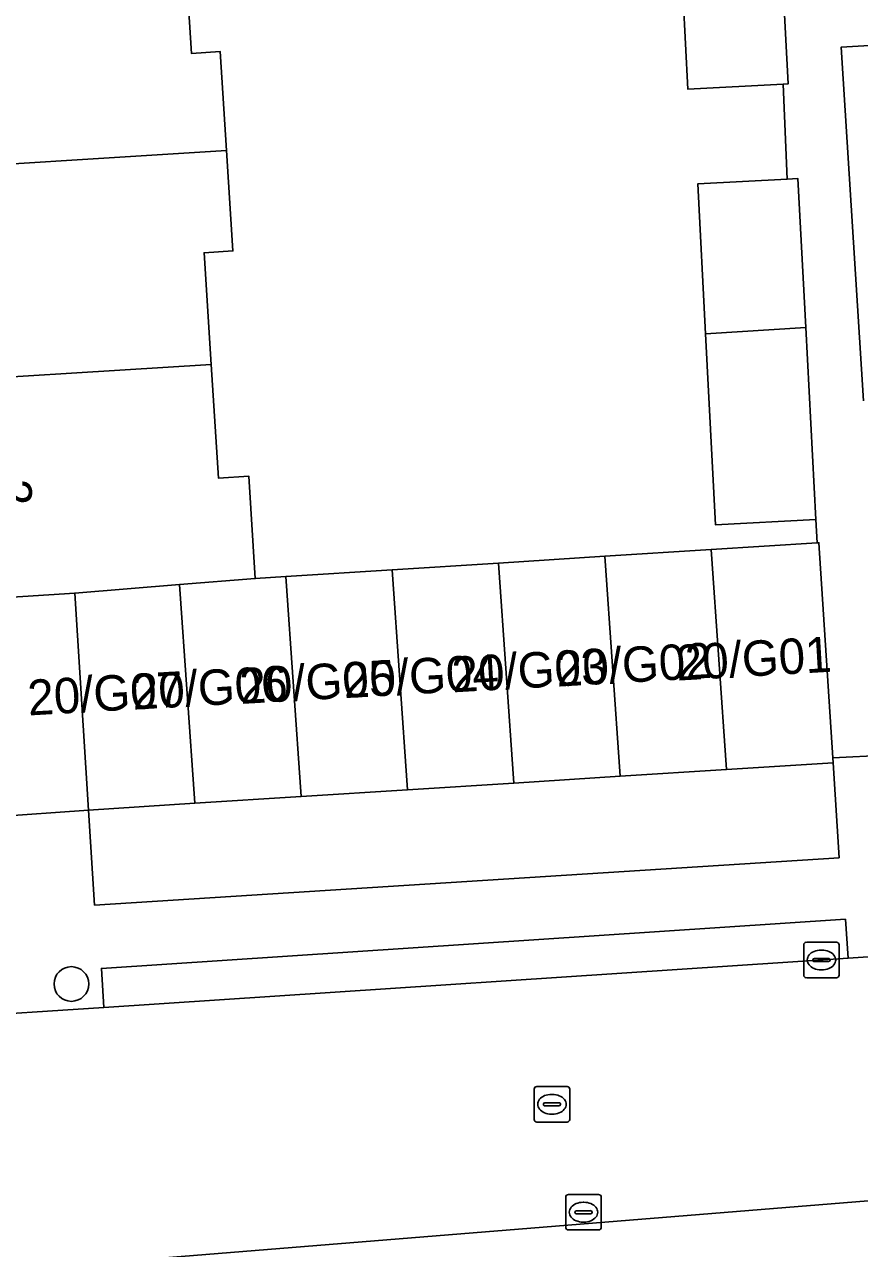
# Model space of a CAD drawing. Extents: x 159680 to 160786, y 387323 to 388340.
# Drawn here: x 160242.97 to 160266.51, y 387825.78 to 387860.29 of the extents above; entities that cross this region are included whole.
import ezdxf

# ---------------------------------------------------------------- set-up
doc = ezdxf.new("R2010")
doc.units = 0
for name, color, linetype in [('IMGEO_Boom', 7, 'Continuous'), ('IMGEO_Erf', 7, 'Continuous'), ('IMGEO_Kolk', 7, 'Continuous'), ('IMGEO_Pand', 7, 'Continuous'), ('IMGEO_Pand_nummerreeks', 7, 'Continuous'), ('IMGEO_Parkeervlak_open', 7, 'Continuous'), ('IMGEO_Rijbaan_lokaal_open', 7, 'Continuous'), ('IMGEO_Rioolput', 7, 'Continuous'), ('IMGEO_Voetpad_open', 7, 'Continuous')]:
    doc.layers.add(name, color=color, linetype=linetype)

msp = doc.modelspace()

# ---------------------------------------------------------------- linework, layer by layer
at = {"layer": 'IMGEO_Boom'}
msp.add_circle((160244.289, 387833.235), 0.489, dxfattribs=at)
at = {"layer": 'IMGEO_Erf'}
for points in [[(160247.466, 387862.725), (160247.672, 387859.477), (160248.484, 387859.529), (160248.662, 387856.736), (160248.842, 387853.906), (160248.032, 387853.854), (160248.232, 387850.704), (160248.436, 387847.502), (160249.288, 387847.556), (160249.471, 387844.669), (160250.333, 387844.724), (160253.332, 387844.914), (160256.33, 387845.105), (160259.328, 387845.295), (160262.327, 387845.486), (160265.313, 387845.676), (160265.271, 387846.329), (160262.449, 387846.182), (160262.168, 387851.571), (160261.948, 387855.798), (160264.463, 387855.929), (160264.358, 387858.608), (160261.669, 387858.468), (160261.402, 387863.592)], [(160239.442, 387837.76), (160244.771, 387838.139), (160244.382, 387844.258), (160239.539, 387843.95), (160239.52, 387844.246), (160239.862, 387844.268), (160239.639, 387847.766), (160238.976, 387847.724), (160238.956, 387848.036), (160239.268, 387848.056), (160239.136, 387850.138), (160239.003, 387852.22), (160238.723, 387852.202), (160238.702, 387852.539), (160239.332, 387852.579), (160239.117, 387855.96), (160238.75, 387855.937), (160238.738, 387856.118), (160238.727, 387856.298), (160239.079, 387856.32), (160238.861, 387859.753)], [(160267.111, 387859.715), (160265.991, 387859.653), (160266.622, 387849.679)]]:
    msp.add_lwpolyline(points, dxfattribs=at)
at = {"layer": 'IMGEO_Kolk'}
for p, q in [((160264.932, 387833.487), (160264.932, 387834.339)), ((160265.007, 387834.413), (160265.859, 387834.413)), ((160265.933, 387834.339), (160265.933, 387833.487)), ((160265.42, 387834.193), (160265.445, 387834.193)), ((160265.191, 387833.907), (160265.191, 387833.919)), ((160265.629, 387833.87), (160265.231, 387833.87)), ((160265.234, 387833.956), (160265.632, 387833.956)), ((160265.443, 387833.633), (160265.418, 387833.633)), ((160265.675, 387833.919), (160265.675, 387833.907)), ((160265.859, 387833.413), (160265.007, 387833.413)), ((160258.225, 387826.374), (160258.225, 387827.226)), ((160258.3, 387827.3), (160259.152, 387827.3)), ((160258.713, 387827.08), (160258.738, 387827.08)), ((160259.226, 387827.226), (160259.226, 387826.374)), ((160258.484, 387826.794), (160258.484, 387826.806)), ((160258.922, 387826.757), (160258.524, 387826.757)), ((160258.527, 387826.843), (160258.925, 387826.843)), ((160258.968, 387826.806), (160258.968, 387826.794)), ((160258.736, 387826.52), (160258.711, 387826.52)), ((160259.152, 387826.3), (160258.3, 387826.3))]:
    msp.add_line(p, q, dxfattribs=at)
for points in [[(160264.932, 387833.487), (160264.932, 387834.339)], [(160265.007, 387834.413), (160265.859, 387834.413)], [(160265.933, 387834.339), (160265.933, 387833.487)], [(160265.859, 387833.413), (160265.007, 387833.413)], [(160258.225, 387826.374), (160258.225, 387827.226)], [(160258.3, 387827.3), (160259.152, 387827.3)], [(160259.226, 387827.226), (160259.226, 387826.374)], [(160259.152, 387826.3), (160258.3, 387826.3)]]:
    msp.add_lwpolyline(points, dxfattribs=at)
for centre, radius, start, end in [((160265.009, 387834.337), 0.0765, 91.552, 178.448), ((160265.009, 387834.337), 0.0765, 91.552, 178.448), ((160265.857, 387834.337), 0.0765, 1.552, 88.448), ((160265.857, 387834.337), 0.0765, 1.552, 88.448), ((160265.231, 387833.916), 0.0403, 85.8775, 175.7526), ((160265.228, 387833.906), 0.0366, 178.938, 274.7102), ((160265.632, 387833.913), 0.043, 264.8664, 352.4533), ((160265.636, 387833.918), 0.0386, 1.7309, 96.639), ((160265.009, 387833.489), 0.0765, 181.552, 268.448), ((160265.009, 387833.489), 0.0765, 181.552, 268.448), ((160265.857, 387833.489), 0.0765, 271.552, 358.448), ((160265.857, 387833.489), 0.0765, 271.552, 358.448), ((160258.302, 387827.224), 0.0765, 91.552, 178.448), ((160258.302, 387827.224), 0.0765, 91.552, 178.448), ((160259.15, 387827.224), 0.0765, 1.552, 88.448), ((160259.15, 387827.224), 0.0765, 1.552, 88.448), ((160258.524, 387826.803), 0.0403, 85.8775, 175.7526), ((160258.521, 387826.793), 0.0366, 178.938, 274.7102), ((160258.925, 387826.8), 0.043, 264.8664, 352.4533), ((160258.929, 387826.805), 0.0386, 1.7309, 96.639), ((160258.302, 387826.376), 0.0765, 181.552, 268.448), ((160258.302, 387826.376), 0.0765, 181.552, 268.448), ((160259.15, 387826.376), 0.0765, 271.552, 358.448), ((160259.15, 387826.376), 0.0765, 271.552, 358.448)]:
    msp.add_arc(centre, radius, start, end, dxfattribs=at)
for centre, major_axis, ratio, start_param, end_param in [((160265.419, 387833.913), (-0.387, 0.002), 0.722429, 4.712389, 7.853982), ((160265.444, 387833.913), (-0.39, 0.002), 0.717154, 1.570796, 4.712389), ((160258.712, 387826.8), (-0.387, 0.002), 0.722429, 4.712389, 7.853982), ((160258.737, 387826.8), (-0.39, 0.002), 0.717154, 1.570796, 4.712389)]:
    msp.add_ellipse(centre, major_axis=major_axis, ratio=ratio, start_param=start_param, end_param=end_param, dxfattribs=at)
at = {"layer": 'IMGEO_Pand'}
for points in [[(160264.223, 387863.767), (160261.402, 387863.592), (160261.669, 387858.468), (160264.358, 387858.608), (160264.491, 387858.615)], [(160238.35, 387862.158), (160238.484, 387860.053), (160238.226, 387860.037), (160238.247, 387859.714), (160238.861, 387859.753), (160239.079, 387856.32), (160238.727, 387856.298), (160238.738, 387856.118), (160248.662, 387856.736), (160248.484, 387859.529), (160247.672, 387859.477), (160247.466, 387862.725)], [(160248.232, 387850.704), (160248.032, 387853.854), (160248.842, 387853.906), (160248.662, 387856.736), (160238.738, 387856.118), (160238.75, 387855.937), (160239.117, 387855.96), (160239.332, 387852.579), (160238.702, 387852.539), (160238.723, 387852.202), (160239.003, 387852.22), (160239.136, 387850.138)], [(160264.771, 387855.945), (160264.463, 387855.929), (160261.948, 387855.798), (160262.168, 387851.571), (160264.989, 387851.747)], [(160262.449, 387846.182), (160265.271, 387846.329), (160264.989, 387851.747), (160262.168, 387851.571)], [(160247.338, 387844.497), (160249.471, 387844.669), (160249.288, 387847.556), (160248.436, 387847.502), (160248.232, 387850.704), (160239.136, 387850.138), (160239.268, 387848.056), (160238.956, 387848.036), (160238.976, 387847.724), (160239.639, 387847.766), (160239.862, 387844.268), (160239.52, 387844.246), (160239.539, 387843.95), (160244.382, 387844.258)], [(160262.761, 387839.282), (160262.327, 387845.486), (160259.328, 387845.295), (160259.763, 387839.092)], [(160265.364, 387845.679), (160265.313, 387845.676), (160262.327, 387845.486), (160262.761, 387839.282), (160265.759, 387839.473), (160265.75, 387839.608)], [(160256.764, 387838.901), (160256.33, 387845.105), (160253.332, 387844.914), (160253.766, 387838.711)], [(160259.763, 387839.092), (160259.328, 387845.295), (160256.33, 387845.105), (160256.764, 387838.901)], [(160250.768, 387838.52), (160250.333, 387844.724), (160249.471, 387844.669), (160247.338, 387844.497), (160247.769, 387838.33)], [(160253.766, 387838.711), (160253.332, 387844.914), (160250.333, 387844.724), (160250.768, 387838.52)], [(160247.769, 387838.33), (160247.338, 387844.497), (160244.382, 387844.258), (160244.771, 387838.139)]]:
    msp.add_lwpolyline(points, close=True, dxfattribs=at)
at = {"layer": 'IMGEO_Parkeervlak_open'}
msp.add_lwpolyline([(160244.771, 387838.139), (160244.941, 387835.461), (160265.93, 387836.796), (160265.759, 387839.473), (160262.761, 387839.282), (160259.763, 387839.092), (160256.764, 387838.901), (160253.766, 387838.711), (160250.768, 387838.52), (160247.769, 387838.33)], close=True, dxfattribs=at)
at = {"layer": 'IMGEO_Rijbaan_lokaal_open'}
for points in [[(160354.228, 387839.686), (160349.958, 387839.416), (160329.439, 387838.117), (160324.666, 387837.815), (160317.074, 387837.334), (160266.183, 387833.964), (160245.208, 387832.575), (160240.867, 387832.288), (160223.948, 387826.779), (160209.059, 387820.866), (160204.164, 387818.945), (160200.731, 387817.531), (160203.311, 387810.942), (160204.906, 387811.553), (160206.204, 387812.07), (160211.413, 387814.145), (160211.647, 387814.331), (160217.867, 387816.742), (160222.756, 387818.637), (160224.129, 387819.169), (160231.248, 387822.058)], [(160245.077, 387825.369), (160245.41, 387825.395), (160267.095, 387827.148), (160267.961, 387827.204), (160284.342, 387828.267)], [(160267.095, 387827.148), (160245.41, 387825.395)]]:
    msp.add_lwpolyline(points, dxfattribs=at)
at = {"layer": 'IMGEO_Rioolput'}
for p, q in [((160257.335, 387829.417), (160257.335, 387830.269)), ((160257.41, 387830.343), (160258.262, 387830.343)), ((160258.336, 387830.269), (160258.336, 387829.417)), ((160257.594, 387829.837), (160257.594, 387829.849)), ((160257.637, 387829.886), (160258.035, 387829.886)), ((160257.823, 387830.123), (160257.848, 387830.123)), ((160258.078, 387829.849), (160258.078, 387829.837)), ((160258.032, 387829.8), (160257.634, 387829.8)), ((160257.846, 387829.563), (160257.821, 387829.563)), ((160258.262, 387829.343), (160257.41, 387829.343))]:
    msp.add_line(p, q, dxfattribs=at)
for points in [[(160257.335, 387829.417), (160257.335, 387830.269)], [(160257.41, 387830.343), (160258.262, 387830.343)], [(160258.336, 387830.269), (160258.336, 387829.417)], [(160258.262, 387829.343), (160257.41, 387829.343)]]:
    msp.add_lwpolyline(points, dxfattribs=at)
for centre, radius, start, end in [((160257.412, 387830.267), 0.0765, 91.552, 178.448), ((160257.412, 387830.267), 0.0765, 91.552, 178.448), ((160258.26, 387830.267), 0.0765, 1.552, 88.448), ((160258.26, 387830.267), 0.0765, 1.552, 88.448), ((160257.634, 387829.846), 0.0403, 85.8775, 175.7526), ((160257.631, 387829.836), 0.0366, 178.938, 274.7102), ((160258.035, 387829.843), 0.043, 264.8664, 352.4533), ((160258.039, 387829.848), 0.0386, 1.7309, 96.639), ((160257.412, 387829.419), 0.0765, 181.552, 268.448), ((160257.412, 387829.419), 0.0765, 181.552, 268.448), ((160258.26, 387829.419), 0.0765, 271.552, 358.448), ((160258.26, 387829.419), 0.0765, 271.552, 358.448)]:
    msp.add_arc(centre, radius, start, end, dxfattribs=at)
for centre, major_axis, ratio, start_param, end_param in [((160257.822, 387829.843), (-0.387, 0.002), 0.722429, 4.712389, 7.853982), ((160257.847, 387829.843), (-0.39, 0.002), 0.717154, 1.570796, 4.712389)]:
    msp.add_ellipse(centre, major_axis=major_axis, ratio=ratio, start_param=start_param, end_param=end_param, dxfattribs=at)
at = {"layer": 'IMGEO_Voetpad_open'}
for points in [[(160267.105, 387861.853), (160265.856, 387861.784), (160265.199, 387872.173), (160264.859, 387877.269), (160264.526, 387882.257), (160263.041, 387882.133), (160263.438, 387875.887), (160263.545, 387874.309), (160263.889, 387869.368), (160263.632, 387869.35), (160263.691, 387868.215), (160263.991, 387868.231), (160264.223, 387863.767), (160264.491, 387858.615), (160264.358, 387858.608), (160264.463, 387855.929), (160264.771, 387855.945), (160264.989, 387851.747), (160265.271, 387846.329), (160265.313, 387845.676), (160265.364, 387845.679), (160265.75, 387839.608), (160267.27, 387839.686)], [(160266.622, 387849.679), (160265.991, 387859.653), (160267.111, 387859.715)], [(160240.867, 387832.288), (160245.208, 387832.575), (160245.135, 387833.673), (160266.11, 387835.062), (160266.183, 387833.964), (160317.074, 387837.334), (160324.666, 387837.815), (160329.439, 387838.117), (160329.41, 387838.616), (160349.929, 387839.915), (160349.958, 387839.416), (160354.228, 387839.686)], [(160267.313, 387839.013), (160267.27, 387839.686), (160265.75, 387839.608), (160265.759, 387839.473), (160265.93, 387836.796), (160244.941, 387835.461), (160244.771, 387838.139), (160239.442, 387837.76)]]:
    msp.add_lwpolyline(points, dxfattribs=at)
msp.add_lwpolyline([(160266.183, 387833.964), (160266.11, 387835.062), (160245.135, 387833.673), (160245.208, 387832.575)], close=True, dxfattribs=at)

# ---------------------------------------------------------------- texts
at = {"layer": 'IMGEO_Pand_nummerreeks'}
for s, rotation, p in [('2', 273.6468, (160242.152, 387847.433)), ('20/G01', 3.3117, (160261.361, 387841.789)), ('20/G03', 3.3139, (160255.041, 387841.457)), ('20/G02', 3.3139, (160257.981, 387841.619)), ('20/G05', 3.3139, (160249.061, 387841.131)), ('20/G04', 3.3139, (160251.98, 387841.294)), ('20/G07', 3.3139, (160243.081, 387840.806)), ('20/G06', 3.3139, (160246.027, 387840.969))]:
    msp.add_text(s, height=1, rotation=rotation, dxfattribs=at).set_placement(p)

doc.saveas('drawing.dxf')
